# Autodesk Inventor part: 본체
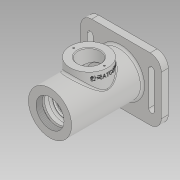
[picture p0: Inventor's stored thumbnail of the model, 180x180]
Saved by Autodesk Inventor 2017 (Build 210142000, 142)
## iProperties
Part Number: 본체
Material: 일반
Document SubType Name: Modeling
Designer: user
Density: 1 g/cm^3
Appearance: 기본값
Author: user
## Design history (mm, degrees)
sketch "스케치2"
  geometry: L1 (-58, -45)-(58, -45); L2 (58, -45)-(58, 45); L3 (58, 45)-(-58, 45); L4 (-58, 45)-(-58, -45); L5 (-58, -45)-(58, 45); L6 (58, -45)-(-58, 45); 1 further point
  constraints: 12 end point, 2 midpoint, 2 parallel, 1 horizontal, 1 perpendicular
  dimensions: "d2" = 90 distance of L1.end L2.end; "d3" = 116 distance of L2.end L3.end
extrude "돌출1" new body sketch "스케치2" distance "d4" = 10; taper "d5" = 0 deg
sketch "스케치3"
  geometry: C1 r 35 at (0, 0); 1 further point
  constraints: 1 centre point, 1 coincident
  dimensions: "d6" = 70 diameter of C1
extrude "돌출2" join sketch "스케치3" distance "d7" = 3; taper "d8" = 0 deg
sketch "스케치4"
  geometry: C1 r 31 at (0, 0); 1 further point
  constraints: 1 centre point, 1 coincident
  dimensions: "d9" = 62 diameter of C1
extrude "돌출3" join sketch "스케치4" distance "d10" = 102; taper "d11" = 0 deg
node "작업 평면1"
sketch "스케치5"
  geometry: L1 (31, 112)-(-31, 112) reference; C1 r 27 at (0, 56); 1 further point
  constraints: 1 centre point, 1 vertical alignment
  dimensions: "d13" = 54 diameter of C1; "d14" = 56 distance from line of L1 C1.centre
extrude "돌출4" join sketch "스케치5" stored distance "d16" = 102; taper "d17" = 0 deg
sketch "스케치6"
  geometry: C1 r 31 at (0, 0) reference; 1 further point
  constraints: 1 coincident
hole "구멍1" sketch "스케치6" at (0, 0) diameter "d18" = 40.376; stored, may be unused: countersink angle "d22" = 90 deg, drill point angle "d24" = 0 deg; dims "d19" = 84, "d20" = 4, "d21" = 2, "d23" = 9
sketch "스케치7"
  geometry: L1 (20.188, 103)-(20.188, 112) reference; L2 (20.188, 103)-(-20.188, 103) reference; L3 (-35, -3)-(35, -3) reference; L4 (0, 103)-(0, -3); L5 (0, 103)-(24, 103); L6 (24, 103)-(24, 100); L7 (24, 100)-(20, 100); L8 (20, 100)-(20, 94); L9 (17, 91)-(17.5, 91); L10 (17.5, 91)-(17.5, 87.75); L11 (17.5, 87.75)-(18.5, 87.75); L12 (18.5, 87.75)-(18.5, 86); L13 (18.5, 86)-(17.5, 86); L14 (17.5, 86)-(17.5, 76); L15 (18.5, 75)-(23, 75); L16 (26, 72)-(26, 40); L17 (23, 37)-(18.5, 37); L18 (17.5, 36)-(17.5, 26.3); L19 (17.2, 26)-(16, 26); L20 (16, 26)-(16, 24); L21 (13, 21)-(10, 21); L22 (10, 21)-(10, 18.3); L23 (10, 18.3)-(12.2, 18.3); L24 (12.5, 18)-(12.5, 11.7); L25 (12.904, 11)-(14.022, 11); L26 (16.779, 9.182)-(22, -3); L27 (17.5, 76)-(18.5, 75); L28 (18.5, 37)-(17.5, 36); L29 (12.5, 11.7)-(12.904, 11); A1 r 3 centre (17, 94) between (17, 91) and (20, 94); A2 r 3 centre (23, 72) between (26, 72) and (23, 75); A3 r 3 centre (23, 40) between (23, 37) and (26, 40); A4 r 0.3 centre (17.2, 26.3) between (17.2, 26) and (17.5, 26.3); A5 r 0.3 centre (12.2, 18) between (12.5, 18) and (12.2, 18.3); A6 r 3 centre (14.022, 8) between (16.779, 9.182) and (14.022, 11); A7 r 3 centre (13, 24) between (13, 21) and (16, 24); 11 further points
  constraints: 52 end point, 24 point on line, 17 perpendicular, 14 point on circle, 14 tangent, 7 centre point, 3 equal radius, 2 horizontal, 2 midpoint, 1 vertical
  dimensions: "d25" = 3 distance of L5.end L6.end; "d26" = 9 distance of L7.end point (20, 91); "d27" = 3.25 distance of L9.end L10.end; "d28" = 1.75 distance of L11.end L12.end; "d29" = 11 distance of L13.end point (17.5, 75); "d30" = 38 distance of point (26, 75) point (26, 37); "d31" = 11 distance of point (17.5, 37) point (17.5, 26); "d32" = 5 distance of L19.end point (16, 21); "d33" = 2.7 distance of L21.end L22.end; "d34" = 7.3 distance of point (12.5, 18.3) point (12.5, 11); "d35" = 48 diameter of L6 L4; "d36" = 40 diameter of L8 L4; "d37" = 35 diameter of L10 L4; "d38" = 37 diameter of L12 L4; "d39" = 52 diameter of L16 L4; "d40" = 35 diameter of L18 L4; "d41" = 32 diameter of L20 L4; "d42" = 20 diameter of L22 L4; "d43" = 25 diameter of L24 L4; "d44" = 44 diameter of L26.end L4; "d45" = 3 radius of A1; "d46" = 1 distance of L14.end point (17.5, 75); "d47" = 1 distance of L15.start point (17.5, 75) (= d46); "d48" = 3 radius of A2; "d49" = 1 distance of L17.end point (17.5, 37); "d50" = 1 distance of L18.start point (17.5, 37) (= d49); "d51" = 0.3 radius of A4; "d52" = 0.7 distance of L24.end point (12.5, 11); "d53" = 30 deg angle of L24 L29; "d54" = 3 radius of A6
revolve "회전1" sketch "스케치7" stored, may be unused: angle "d55" = 90 deg
sketch "스케치8"
  geometry: C1 r 27 at (0, 0) reference; C2 r 16 at (0, 0); 1 further point
  constraints: 1 centre point, 1 coincident
  dimensions: "d56" = 32 diameter of C2
extrude "돌출5" cut sketch "스케치8" stored distance "d57" = 102; taper "d58" = 0 deg
sketch "스케치9"
  geometry: C1 r 16 at (0, 0) reference; C2 r 27 at (0, 0) reference; A1 r 22 centre (0, 0) between (-22, 0) and (22, 0); 1 further point
  constraints: 2 horizontal alignment, 2 point on circle, 1 centre point, 1 coincident
  dimensions: "d59" = 44 diameter of A1
hole "구멍2" sketch "스케치9" at (-22, 0), (22, 0) diameter "d60" = 2.459; stored, may be unused: countersink angle "d64" = 90 deg, drill point angle "d66" = 118 deg; dims "d61" = 6, "d62" = 4, "d63" = 2, "d65" = 8
sketch "스케치10"
  geometry: L1 (-44, 25)-(-44, -25); L2 (-48, 25)-(-48, -25); L3 (-40, -25)-(-40, 25); L4 (44, 25)-(44, -25); L5 (40, 25)-(40, -25); L6 (48, -25)-(48, 25); C1 r 31 at (0, 0) reference; A1 r 4 centre (-44, 25) between (-40, 25) and (-48, 25); A2 r 4 centre (-44, -25) between (-48, -25) and (-40, -25); A3 r 4 centre (44, 25) between (48, 25) and (40, 25); A4 r 4 centre (44, -25) between (40, -25) and (48, -25); 2 further points
  constraints: 16 end point, 8 point on circle, 8 tangent, 4 centre point, 3 parallel, 2 horizontal alignment, 2 midpoint, 1 vertical
  dimensions: "d67" = 88 distance of L4.start L1.start; "d68" = 44 horizontal distance of L4.start C1.centre; "d69" = 4 radius of A3; "d70" = 50 distance of L4.start L4.end; "d71" = 50 distance of L1.start L1.end; "d72" = 4 radius of A1
extrude "돌출6" cut sketch "스케치10" distance "d73" = 102; taper "d74" = 0 deg
chamfer "모따기1" distance "d75" = 1; stored, may be unused: second distance "d76" = 2, angle "d77" = 45 deg
fillet "모깎기1" dims "d78" = 3
node "작업 평면2"
sketch "스케치11"
  geometry: L1 (42, 83)-(42, 29) reference; 3 further points
  constraints: 1 horizontal alignment, 1 midpoint, 1 other
  dimensions: "d80" = 8 distance from line of point (34, 56) L1
feature "엠보싱1" sketch "스케치11" dims "d2" = 90, "d3" = 116, "d81" = 0.5, "d82" = 0
fillet "모깎기2" dims "d83" = 16
node "솔리드1"
other parameters: "d12" = 42
